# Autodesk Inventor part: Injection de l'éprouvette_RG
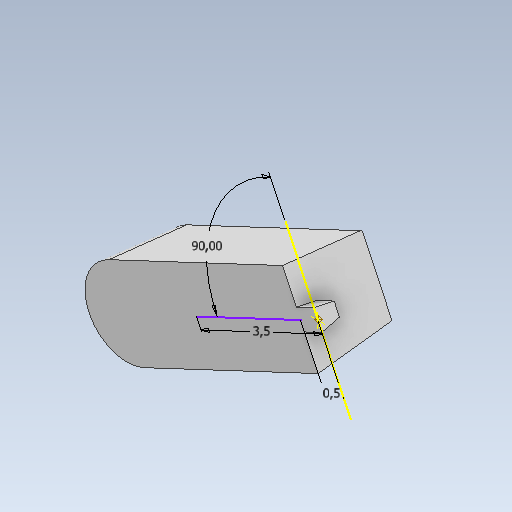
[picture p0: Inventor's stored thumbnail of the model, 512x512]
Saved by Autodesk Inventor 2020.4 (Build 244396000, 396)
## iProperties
Created: 2021-10
Part Number: Injection de l'éprouvette_RG
Material: Générique
Document SubType Name: Modeling
Designer: mel
Density: 1 g/cm^3
Appearance: Par défaut
Author: mel
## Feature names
1. Balayage1
2. Révolution1 [Revolution]
3. Extrusion1
4. Lissage2
## Parameters: d0 = 0, d1 = 3.5 mm, d2 = 90 deg, d3 = 0.5 mm, d4 = 2.18262 mm, d5 = 2 mm, d6 = 85 deg, d7 = 85 deg, d8 = 0.05 mm, d9 = 0, d10 = 0, d11 = 2 mm, d12 = 1.09131 mm, d13 = 2 mm, d14 = 85 deg, d15 = 0.05 mm, d16 = 180 deg, d17 = 2.18262 mm, d18 = 2 mm, d19 = 85 deg, d20 = 85 deg, d21 = 0.05 mm, d22 = 2 mm, d23 = 0, d42 = 0.5 mm, d43 = 0.5 mm, d44 = 80 deg, d45 = 80 deg, d46 = 0.5 mm, d47 = 0.5 mm, d48 = 80 deg, d49 = 80 deg, d50 = 0, d51 = 90 deg, d52 = 0, d53 = 90 deg, d54 = 0.1 mm, d55 = 0.1 mm
